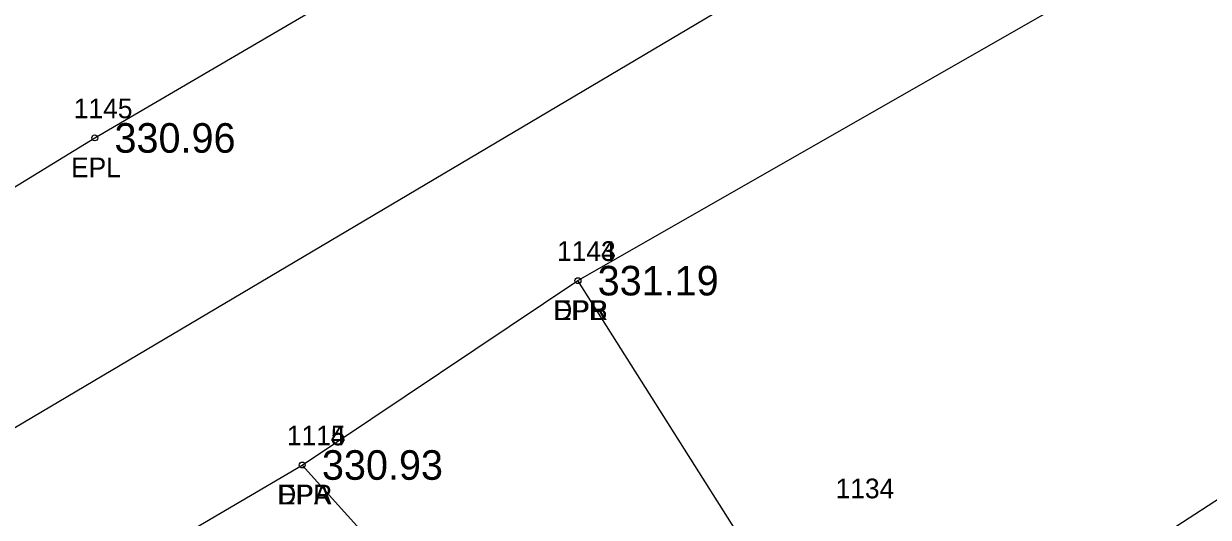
# Model space of a CAD drawing. Extents: x 2231119 to 2232595, y 1035731 to 1037094.
# Drawn here: x 2231678 to 2231738, y 1036500.6 to 1036525.6 of the extents above; entities that cross this region are included whole.
import ezdxf

# ---------------------------------------------------------------- set-up
doc = ezdxf.new("R2010")
doc.units = 0
for name, color, linetype in [('RD_EX_DR_Pipe_txCode', 7, 'Continuous'), ('RD_EX_Driveway', 7, 'Continuous'), ('RD_EX_Driveway_txCode', 7, 'Continuous'), ('RD_EX_Road', 7, 'Continuous'), ('RD_EX_Road_txCode', 7, 'Continuous'), ('RD_EX_TX_Driveway_ELEV', 7, 'Continuous'), ('RD_EX_TX_Road_ELEV', 7, 'Continuous'), ('RD_EX_VEG', 7, 'Continuous'), ('RD_HC_Cl', 7, 'Continuous'), ('RD_SMD_Locator', 7, 'Continuous')]:
    doc.layers.add(name, color=color, linetype=linetype)

msp = doc.modelspace()

# ---------------------------------------------------------------- linework, layer by layer
at = {"layer": 'RD_EX_Driveway'}
for points in [[(2231739.186, 1036472.896), (2231720.317, 1036490.052), (2231706.071, 1036512.594)], [(2231692.093, 1036503.238), (2231712.625, 1036480.399), (2231730.963, 1036467.852)]]:
    msp.add_lwpolyline(points, dxfattribs=at)
at = {"layer": 'RD_EX_Road'}
for points in [[(2231606.098, 1036462.918), (2231601.274, 1036470.818), (2231681.578, 1036519.838), (2231764.985, 1036568.781), (2231851.504, 1036619.946), (2231935.622, 1036669.654), (2232021.78, 1036720.22), (2232106.749, 1036770.574), (2232190.543, 1036819.198), (2232275.917, 1036870.266)], [(2231606.098, 1036462.918), (2231610.57, 1036455.357), (2231692.093, 1036503.238), (2231706.071, 1036512.594), (2231777.095, 1036553.27), (2231861.393, 1036604.653), (2231946.389, 1036654.771), (2232031.075, 1036704.2), (2232117.063, 1036755.157), (2232199.91, 1036803.805), (2232286.695, 1036855.364)]]:
    msp.add_lwpolyline(points, dxfattribs=at)
at = {"layer": 'RD_EX_VEG'}
msp.add_lwpolyline([(2231753.591, 1036474.982), (2231730.547, 1036496.345), (2231788.451, 1036533.865), (2231871.454, 1036588.786), (2231958.943, 1036639.514), (2232040.643, 1036687.925), (2232130.591, 1036740.479), (2232213.065, 1036784.391), (2232299.538, 1036835.553)], dxfattribs=at)
at = {"layer": 'RD_HC_Cl'}
msp.add_line((2231548.98, 1036428.871), (2232281.057, 1036863.235), dxfattribs=at)
at = {"layer": 'RD_SMD_Locator'}
for centre in [(2231681.578, 1036519.838), (2231706.071, 1036512.594), (2231706.071, 1036512.594), (2231692.093, 1036503.238), (2231692.093, 1036503.238)]:
    msp.add_circle(centre, 0.15, dxfattribs=at)

# ---------------------------------------------------------------- texts
at = {"layer": 'RD_EX_DR_Pipe_txCode'}
msp.add_text('1134', height=1, dxfattribs=at).set_placement((2231719.13, 1036501.548))
at = {"layer": 'RD_EX_Driveway_txCode'}
for s, p in [('1143', (2231705.008, 1036513.594)), ('DPB', (2231704.819, 1036510.594)), ('1115', (2231691.314, 1036504.238)), ('DPA', (2231690.826, 1036501.238))]:
    msp.add_text(s, height=1, dxfattribs=at).set_placement(p)
at = {"layer": 'RD_EX_Road_txCode'}
for s, p in [('1145', (2231680.515, 1036520.838)), ('EPL', (2231680.373, 1036517.838)), ('1144', (2231705.008, 1036513.594)), ('EPR', (2231704.843, 1036510.594)), ('1114', (2231691.314, 1036504.238)), ('EPR', (2231690.865, 1036501.238))]:
    msp.add_text(s, height=1, dxfattribs=at).set_placement(p)
at = {"layer": 'RD_EX_TX_Driveway_ELEV'}
for s, p in [('331.19', (2231707.071, 1036511.844)), ('330.93', (2231693.093, 1036502.488))]:
    msp.add_text(s, height=1.5, dxfattribs=at).set_placement(p)
at = {"layer": 'RD_EX_TX_Road_ELEV'}
for s, p in [('330.96', (2231682.578, 1036519.088)), ('331.19', (2231707.071, 1036511.844)), ('330.93', (2231693.093, 1036502.488))]:
    msp.add_text(s, height=1.5, dxfattribs=at).set_placement(p)

doc.saveas('drawing.dxf')
